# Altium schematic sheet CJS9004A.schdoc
size 127 x 101 mm
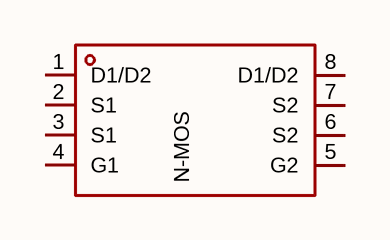
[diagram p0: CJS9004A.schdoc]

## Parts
Q?  cjs9004a  [TSSOP-8_L4.4-W3.0-P0.65-LS6.4-BL]  (value not drawn)

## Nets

Not connected (* = marked no-connect by the designer): Q? 1(D1/D2) 2(S1) 3(S1) 4(G1) 5(G2) 6(S2) 7(S2) 8(D1/D2)

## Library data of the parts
Q? = cjs9004a: 数量:2个N沟道;漏源电压(Vdss):20V;连续漏极电流(Id):10A;导通电阻(RDS(on)):11mΩ@2.5V;耗散功率(Pd):2W;阈值电压(Vgs(th)):1V;; Manufacturer: CJ(江苏长电/长晶); AddInBom: yes; ModelId: 85577802f9634e7e85ffa2fd25a37b6f; ModelName: TSSOP-8_L4.4-W3.0-P0.65-LS6.4-BL-2; ModelTransform: 118.11,251.968,0,0,0,0,0,0,0; Number: 2个N沟道; Drain to Source Voltage: 20V; Current - Continuous Drain(Id): 10A; Pd - Power Dissipation: 2W; Gate Threshold Voltage (Vgs(th)): 1V; Gate Charge(Qg): 15nC@4.5V; Input Capacitance(Ciss): 1.258nF; Reverse Transfer Capacitance (Crss@Vds): 51pF; Configuration: 共漏; Type: N沟道; Output Capacitance(Coss): 193pF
